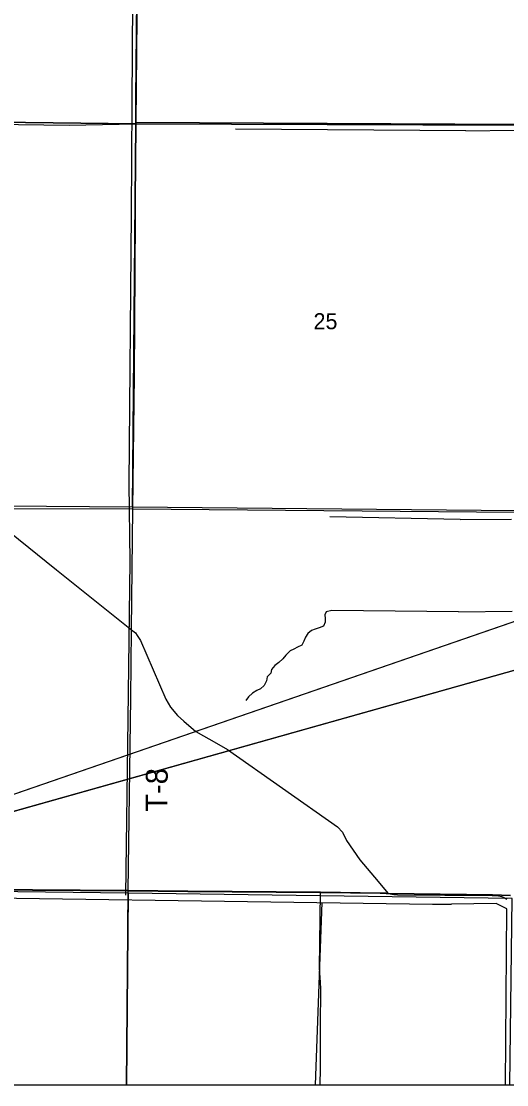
# Model space of a CAD drawing. Extents: x -6.2 to 37.4, y 0.2 to 22.2.
# Drawn here: x 6.55 to 7.181, y 14.307 to 15.692 of the extents above; entities that cross this region are included whole.
import ezdxf

# ---------------------------------------------------------------- set-up
doc = ezdxf.new("R2010")
doc.units = 0
for name, color, linetype in [('GM_X_County_Road', 7, 'Continuous'), ('GM_X_Minor_River', 7, 'Continuous'), ('GM_X_Rail_Line', 7, 'Continuous'), ('GM_X_Section', 7, 'Continuous'), ('GM_X_Section_Text', 7, 'Continuous'), ('GM_X_Township_Road', 7, 'Continuous'), ('GM_X_Township_Road_Text', 7, 'Continuous'), ('GM_X_US_Shield', 7, 'Continuous'), ('SH_Border', 7, 'Continuous'), ('SH_Cut_Line', 7, 'Continuous'), ('SH_Data', 7, 'Continuous')]:
    doc.layers.add(name, color=color, linetype=linetype)

msp = doc.modelspace()

# ---------------------------------------------------------------- linework, layer by layer
at = {"layer": 'GM_X_County_Road'}
msp.add_lwpolyline([(6.4966, 15.0575), (6.5957, 14.9778), (6.6934, 14.8996), (6.6984, 14.8956), (6.7008, 14.8921), (6.705, 14.8856), (6.7378, 14.8096), (6.7441, 14.7988), (6.753, 14.7883), (6.7612, 14.7807), (6.777, 14.7672), (6.8039, 14.7522), (6.818, 14.744), (6.9612, 14.643), (6.9679, 14.6363), (6.9729, 14.6254), (6.9904, 14.6001), (7.0094, 14.5778), (7.0273, 14.5562)], dxfattribs=at)
at = {"layer": 'GM_X_Minor_River'}
for p, q in [((7.1283, 15.5492), (7.191, 15.5501)), ((7.1207, 15.0435), (7.1876, 15.0437)), ((7.1186, 14.9231), (7.1883, 14.9241)), ((6.9406, 14.5446), (6.9321, 14.3074))]:
    msp.add_line(p, q, dxfattribs=at)
for points in [[(6.686, 14.5543), (6.6888, 14.7834), (6.6917, 14.9892), (6.6902, 15.0896), (6.6931, 15.4411), (6.6941, 15.5853), (6.695, 15.7201), (6.6955, 15.7245), (6.6966, 15.726), (6.6999, 15.7274)], [(7.1283, 15.5492), (6.8283, 15.5515)], [(7.1207, 15.0435), (6.9511, 15.0466)], [(6.9539, 14.925), (6.9463, 14.9232), (6.9449, 14.9191), (6.9452, 14.9144), (6.9451, 14.9096), (6.9429, 14.9044), (6.9375, 14.9022), (6.9323, 14.9004), (6.9275, 14.8986), (6.9227, 14.8949), (6.9194, 14.89), (6.9174, 14.8848), (6.9146, 14.8799), (6.9091, 14.8771), (6.9042, 14.8746), (6.8995, 14.8722), (6.894, 14.8668), (6.8903, 14.8618), (6.8849, 14.8571), (6.8795, 14.8531), (6.8752, 14.8482), (6.8743, 14.8433), (6.8699, 14.8383), (6.869, 14.8332), (6.866, 14.8273), (6.8612, 14.8229), (6.8562, 14.8205), (6.8506, 14.8174), (6.8454, 14.8126), (6.8421, 14.8075)], [(7.1186, 14.9231), (6.9539, 14.925)], [(6.3025, 14.5539), (7.0849, 14.5425), (7.1095, 14.5424)], [(7.1796, 14.3074), (7.1813, 14.5366), (7.1677, 14.5434), (7.1094, 14.5424)]]:
    msp.add_lwpolyline(points, dxfattribs=at)
at = {"layer": 'GM_X_Rail_Line'}
for points in [[(7.1861, 14.554), (7.1627, 14.5545), (7.0271, 14.5564), (7.0244, 14.5567), (7.0166, 14.557), (6.9389, 14.5582), (6.7664, 14.5594), (6.6888, 14.5602), (6.5644, 14.561), (6.4587, 14.5616), (6.4366, 14.5618), (6.3613, 14.5626), (6.2975, 14.5634), (6.1887, 14.5642), (6.188, 14.5642), (6.1064, 14.5648), (5.9991, 14.5656), (5.9261, 14.5666), (5.853, 14.567), (5.7893, 14.5675), (5.6862, 14.5684), (5.5688, 14.5693)], [(5.5688, 14.5693), (5.6862, 14.5684), (5.7893, 14.5675), (5.853, 14.567), (5.9261, 14.5666), (5.9991, 14.5656), (6.1064, 14.5648), (6.188, 14.5642), (6.1887, 14.5642), (6.2975, 14.5634), (6.3613, 14.5626), (6.4366, 14.5618), (6.4587, 14.5616), (6.5644, 14.561), (6.6888, 14.5602), (6.7664, 14.5594), (6.9389, 14.5582), (7.0166, 14.557), (7.0244, 14.5567), (7.0271, 14.5564), (7.1627, 14.5545), (7.1861, 14.554)], [(5.0809, 14.3074), (7.1878, 14.3074)]]:
    msp.add_lwpolyline(points, dxfattribs=at)
at = {"layer": 'GM_X_Section'}
for points in [[(6.7037, 16.063), (6.6989, 15.5603), (6.6989, 15.5584), (6.1968, 15.5647), (6.201, 16.0668)], [(7.201, 16.0586), (7.2008, 16.0497), (7.1968, 15.5575), (6.6989, 15.5603), (6.7037, 16.063)], [(6.1968, 15.5647), (6.6989, 15.5584), (6.6946, 15.0595), (6.1906, 15.0632)], [(6.6989, 15.5603), (7.1968, 15.5575), (7.1967, 15.5531), (7.1969, 15.5497), (7.1936, 15.0544), (6.6946, 15.0595), (6.6989, 15.5584)]]:
    msp.add_lwpolyline(points, close=True, dxfattribs=at)
at = {"layer": 'GM_X_Township_Road'}
for p, q in [((6.6987, 15.5585), (7.1965, 15.5566)), ((6.6951, 15.0571), (7.192, 15.0527))]:
    msp.add_line(p, q, dxfattribs=at)
for points in [[(6.6889, 14.56), (6.6925, 14.8112), (6.6934, 14.8996), (6.6951, 15.0571), (6.697, 15.231), (6.6983, 15.4359), (6.6987, 15.5585), (6.6989, 15.5906), (6.7024, 15.94), (6.7028, 16.0598)], [(6.1957, 15.5633), (6.3943, 15.5597), (6.4474, 15.559), (6.6121, 15.5566), (6.6987, 15.5585)], [(6.1917, 15.0602), (6.4453, 15.0577), (6.4966, 15.0575), (6.6951, 15.0571)], [(6.4367, 14.5616), (6.4588, 14.5614), (6.5645, 14.5607), (6.6889, 14.56)], [(6.687, 14.3074), (6.6873, 14.3476), (6.6881, 14.4455), (6.6885, 14.5108), (6.6889, 14.56)], [(6.6889, 14.56), (6.7665, 14.5591), (6.939, 14.5579)], [(6.9389, 14.3407), (6.9391, 14.3831), (6.9395, 14.4328), (6.9391, 14.4405), (6.9381, 14.4529), (6.9379, 14.4591), (6.939, 14.5579)], [(6.939, 14.5579), (7.0168, 14.5567), (7.0245, 14.5564), (7.0273, 14.5562)], [(7.0273, 14.5562), (7.0346, 14.5551), (7.0393, 14.5547), (7.1622, 14.554), (7.1671, 14.5536), (7.1707, 14.5533), (7.173, 14.553), (7.1745, 14.5525), (7.1759, 14.552), (7.1774, 14.5513), (7.1794, 14.5503), (7.1813, 14.5491)], [(6.9385, 14.3074), (6.9389, 14.3287), (6.9389, 14.3407)]]:
    msp.add_lwpolyline(points, dxfattribs=at)
at = {"layer": 'GM_X_US_Shield'}
for points in [[(6.185, 14.3074), (6.6867, 14.3074), (6.6887, 14.557), (6.1868, 14.5627)], [(6.6867, 14.3074), (7.1853, 14.3074), (7.1882, 14.55), (6.6887, 14.557)]]:
    msp.add_lwpolyline(points, close=True, dxfattribs=at)
at = {"layer": 'SH_Border'}
for p, q in [((6.1881, 14.564), (8.9944, 15.5335)), ((8.9944, 15.3553), (6.1881, 14.564))]:
    msp.add_line(p, q, dxfattribs=at)
at = {"layer": 'SH_Cut_Line'}
for points in [[(7.1861, 14.554), (7.1627, 14.5545), (7.0271, 14.5564), (7.0244, 14.5567), (7.0166, 14.557), (6.9389, 14.5582), (6.7664, 14.5594), (6.6888, 14.5602), (6.5644, 14.561), (6.4587, 14.5616), (6.4366, 14.5618), (6.3613, 14.5626), (6.2975, 14.5634), (6.1887, 14.5642), (6.188, 14.5642), (6.1064, 14.5648), (5.9991, 14.5656), (5.9261, 14.5666), (5.853, 14.567), (5.7893, 14.5675), (5.6862, 14.5684), (5.5688, 14.5693)], [(5.5688, 14.5693), (5.6862, 14.5684), (5.7893, 14.5675), (5.853, 14.567), (5.9261, 14.5666), (5.9991, 14.5656), (6.1064, 14.5648), (6.188, 14.5642), (6.1887, 14.5642), (6.2975, 14.5634), (6.3613, 14.5626), (6.4366, 14.5618), (6.4587, 14.5616), (6.5644, 14.561), (6.6888, 14.5602), (6.7664, 14.5594), (6.9389, 14.5582), (7.0166, 14.557), (7.0244, 14.5567), (7.0271, 14.5564), (7.1627, 14.5545), (7.1861, 14.554)], [(5.0809, 14.3074), (8.4809, 14.3074)]]:
    msp.add_lwpolyline(points, dxfattribs=at)
at = {"layer": 'SH_Data'}
msp.add_line((1.6809, 14.3074), (8.4809, 14.3074), dxfattribs=at)
msp.add_lwpolyline([(8.9944, 15.3553), (6.1881, 14.564), (8.9944, 15.5335)], close=True, dxfattribs=at)

# ---------------------------------------------------------------- texts
at = {"layer": 'GM_X_Section_Text'}
msp.add_text('25', height=0.02093, rotation=0, dxfattribs=at).set_placement((6.93, 15.291))
at = {"layer": 'GM_X_Township_Road_Text'}
msp.add_text('T-8', height=0.02841, rotation=89.5228, dxfattribs=at).set_placement((6.7399, 14.6626))

doc.saveas('drawing.dxf')
